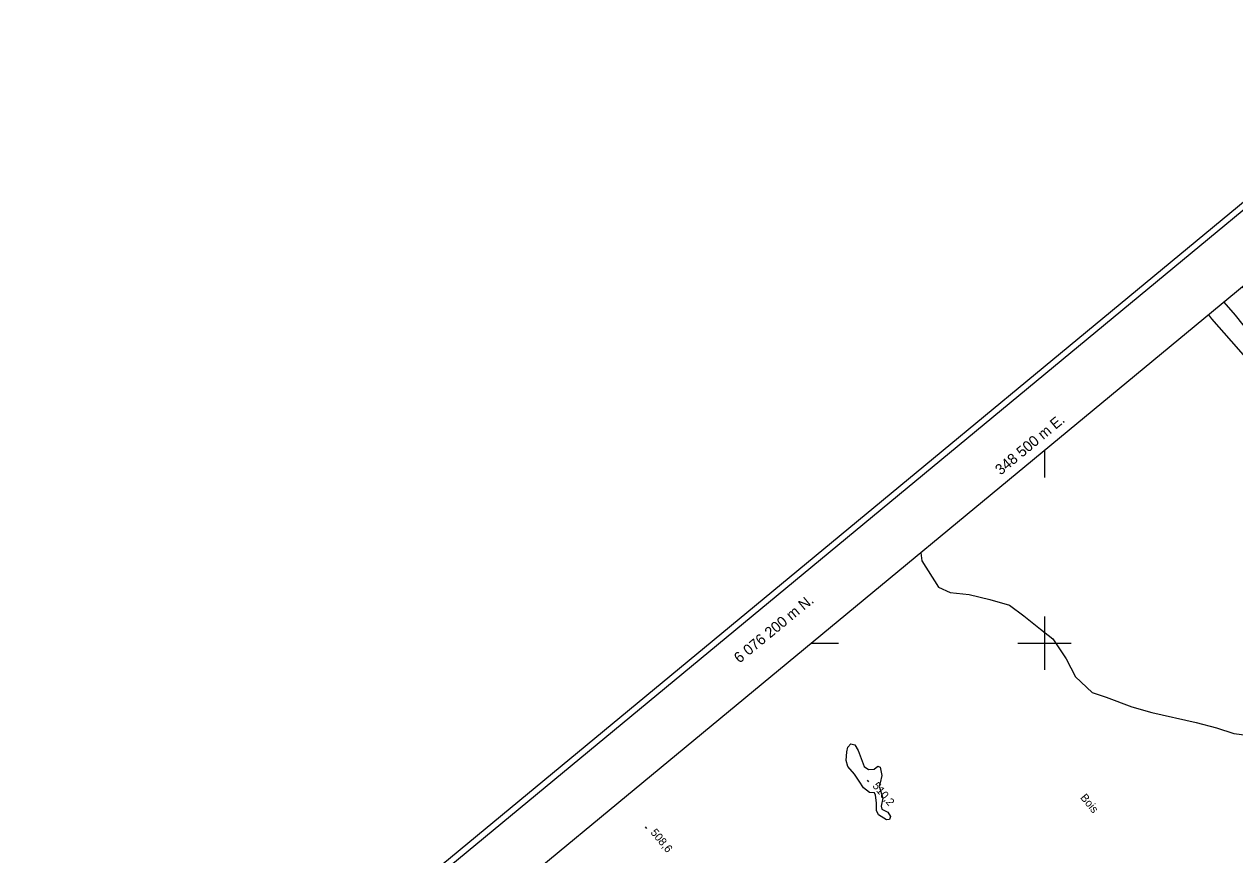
# Model space of a CAD drawing. Extents: x 347312 to 350503, y 6073086 to 6076432.
# Drawn here: x 348117.6 to 348571.4, y 6076120.7 to 6076431.9 of the extents above; entities that cross this region are included whole.
import ezdxf

# ---------------------------------------------------------------- set-up
doc = ezdxf.new("R2010")
doc.units = 0
for name, color, linetype in [('Level 1', 7, 'Continuous'), ('Level 2', 7, 'Continuous'), ('Level 3', 7, 'Continuous'), ('Level 44', 7, 'Continuous'), ('Level 60', 7, 'Continuous'), ('Level 61', 7, 'Continuous')]:
    doc.layers.add(name, color=color, linetype=linetype)

msp = doc.modelspace()

# ---------------------------------------------------------------- linework, layer by layer
at = {"layer": 'Level 1'}
msp.add_lwpolyline([(348428.87, 6076150.93), (348426.3, 6076153.75), (348425.67, 6076156.05), (348425.91, 6076159.24), (348426.33, 6076160.96), (348427.52, 6076162.26), (348428.95, 6076161.86), (348430.19, 6076159.8), (348432.51, 6076153.8), (348434.1, 6076152.59), (348436.16, 6076152.73), (348437.63, 6076153.86), (348438.48, 6076153.5), (348439.12, 6076150.39), (348438.48, 6076147.67), (348438.09, 6076146.39), (348439.43, 6076141.84), (348438.77, 6076138.83), (348439.13, 6076137.78), (348441.38, 6076136.59), (348442.28, 6076135.07), (348441.91, 6076133.93), (348440.8, 6076133.79), (348437.8, 6076135.69), (348437.12, 6076137.27), (348437.11, 6076140.12), (348436.67, 6076142.99), (348436.37, 6076143.82), (348434.41, 6076144.03), (348432.27, 6076145.72), (348430.64, 6076148.25), (348428.87, 6076150.93)], dxfattribs=at)
at = {"layer": 'Level 2'}
for points in [[(348567.29, 6076327.67), (348571.53, 6076322.85), (348580.2, 6076312.03), (348587.57, 6076303.5), (348590.35, 6076300.43), (348592.35, 6076299.7), (348593.84, 6076300.39), (348593.89, 6076301.57), (348592.54, 6076304.23), (348586.64, 6076314.71), (348583.99, 6076319.52), (348581.24, 6076323.97), (348577.14, 6076329.18), (348574.38, 6076333.49), (348574.36, 6076333.51)], [(348561.54, 6076322.91), (348562.63, 6076321.5), (348570.07, 6076313.05), (348579.06, 6076302.81), (348588.96, 6076290.08), (348595.72, 6076280.36), (348604.12, 6076267.16), (348623.47, 6076239.38), (348629.95, 6076233.78), (348632.07, 6076232.6), (348634.38, 6076233.36), (348635.01, 6076235.68), (348633.72, 6076237.97), (348630.36, 6076243.12), (348626.62, 6076249.99), (348623.09, 6076256.76), (348616.92, 6076268.49), (348612.38, 6076276.58), (348605.85, 6076288.26), (348601.82, 6076295.29), (348599.87, 6076300.56), (348599.33, 6076306.09), (348599.51, 6076309.51)], [(348453.72, 6076233.82), (348454.05, 6076230.77), (348460.26, 6076220.88), (348464.66, 6076218.96), (348471.77, 6076218.19), (348479.59, 6076216.29), (348486.91, 6076214.2), (348492.32, 6076210.18), (348498.57, 6076205.16), (348503.16, 6076201.58), (348508.14, 6076194.05), (348511.69, 6076187.34), (348517.87, 6076181.51), (348523.18, 6076179.75), (348532.73, 6076176.16), (348540.24, 6076174.01), (348556.85, 6076170.22), (348564.58, 6076168.26), (348570.99, 6076166.08), (348583.59, 6076164.47)]]:
    msp.add_lwpolyline(points, dxfattribs=at)
at = {"layer": 'Level 3'}
for p, q in [((348433.58, 6076148.62), (348434.09, 6076148)), ((348350.4, 6076131.15), (348350.91, 6076130.53))]:
    msp.add_line(p, q, dxfattribs=at)
at = {"layer": 'Level 60'}
for p, q in [((348500, 6076272.06), (348500, 6076262.06)), ((348412.79, 6076200), (348422.79, 6076200))]:
    msp.add_line(p, q, dxfattribs=at)
msp.add_lwpolyline([(348655.35, 6076431.86), (347312.14, 6075321.93)], dxfattribs=at)
for points in [[(349159.76, 6073089.49), (347315.28, 6075321.63), (348655.04, 6076428.72), (350499.52, 6074196.58)], [(348779.44, 6073584.28), (350085.28, 6074663.34), (348652.09, 6076397.74), (347346.25, 6075318.68)]]:
    msp.add_lwpolyline(points, close=True, dxfattribs=at)
at = {"layer": 'Level 61'}
for p, q in [((348500, 6076210), (348500, 6076190)), ((348490, 6076200), (348510, 6076200))]:
    msp.add_line(p, q, dxfattribs=at)

# ---------------------------------------------------------------- texts
at = {"layer": 'Level 3'}
for s, p in [('510,2', (348435.39, 6076146.38)), ('508,6', (348352.21, 6076128.91))]:
    msp.add_text(s, height=3, rotation=309.5679, dxfattribs=at).set_placement(p)
at = {"layer": 'Level 44'}
msp.add_text('Bois', height=3, rotation=309.568, dxfattribs=at).set_placement((348513.3, 6076142.01))
at = {"layer": 'Level 61'}
for s, rotation, p in [('348 500 m E. ', 39.813, (348483.61, 6076262.71)), ('6 076 200 m N.', 39.3644, (348385.69, 6076192.25))]:
    msp.add_text(s, height=4, rotation=rotation, dxfattribs=at).set_placement(p)

doc.saveas('drawing.dxf')
